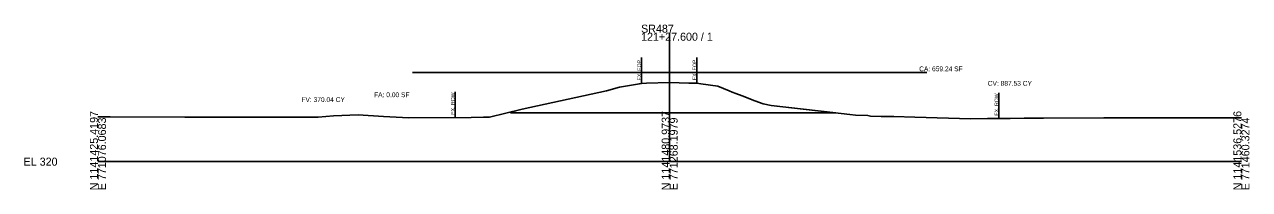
# Model space of a CAD drawing. Extents: x -26 to 5403, y -13 to 9553.
# Drawn here: x 1974.3 to 2402.8, y 1490.3 to 1547.8 of the extents above; entities that cross this region are included whole.
import ezdxf

# ---------------------------------------------------------------- set-up
doc = ezdxf.new("R2010")
doc.units = 0
for name, color, linetype in [('CONST_LV3', 7, 'Continuous'), ('Default', 7, 'Continuous'), ('Draft_XS_Grid', 7, 'Continuous'), ('DTM_X_GROUND', 7, 'Continuous'), ('X_ROW', 7, 'Continuous'), ('X_TRANS_EOP', 7, 'Continuous'), ('XS_CELL', 7, 'Continuous'), ('XS_M_SHAPES_EARTHWORK', 7, 'Continuous'), ('XS_P_GROUND', 7, 'Continuous'), ('XS_SHEET_EW_TX_AREA', 7, 'Continuous'), ('XS_SHEET_EW_TX_VOLUME', 7, 'Continuous')]:
    doc.layers.add(name, color=color, linetype=linetype)

msp = doc.modelspace()

# ---------------------------------------------------------------- linework, layer by layer
at = {"layer": 'CONST_LV3'}
msp.add_lwpolyline([(2110, 1531.09), (2203.61, 1531.09), (2290, 1531.09)], dxfattribs=at)
at = {"layer": 'Default'}
msp.add_lwpolyline([(2258.16, 1517), (2144.29, 1517)], dxfattribs=at)
at = {"layer": 'DTM_X_GROUND'}
msp.add_lwpolyline([(2000, 1515.63), (2004.26, 1515.65), (2030.42, 1515.57), (2031.08, 1515.57), (2032.62, 1515.56), (2045.53, 1515.52), (2050.03, 1515.5), (2067.52, 1515.52), (2074.21, 1515.55), (2076.99, 1515.58), (2082.43, 1515.96), (2091.05, 1516.39), (2099.92, 1515.74), (2108.8, 1515.28), (2130.54, 1515.41), (2134.86, 1515.5), (2136.99, 1515.54), (2148.35, 1518.28), (2177.9, 1524.71), (2182.46, 1525.99), (2189.4, 1527.21), (2190.2, 1527.3), (2191.87, 1527.35), (2199.91, 1527.6), (2206.67, 1527.43), (2209.54, 1527.39), (2210.87, 1527.18), (2216.89, 1526.37), (2220.82, 1524.67), (2221.82, 1524.28), (2223.15, 1523.78), (2225.37, 1522.99), (2229.75, 1521.28), (2232.68, 1520.13), (2235.47, 1519.6), (2263.04, 1516.44), (2264.99, 1516.28), (2269.3, 1516.15), (2270.3, 1515.84), (2274.04, 1515.78), (2278.41, 1515.75), (2285.77, 1515.55), (2305.39, 1514.92), (2311.2, 1515.01), (2319.17, 1515.08), (2323.96, 1515.12), (2327.61, 1515.13), (2330.72, 1515.15), (2351.86, 1515.27), (2400, 1515.35)], dxfattribs=at)
at = {"layer": 'X_ROW'}
for p, q in [((2125, 1524.37), (2125, 1515.37)), ((2315.18, 1524.04), (2315.18, 1515.04))]:
    msp.add_line(p, q, dxfattribs=at)
at = {"layer": 'X_TRANS_EOP'}
for p, q in [((2190.2, 1536.3), (2190.2, 1527.3)), ((2209.54, 1536.39), (2209.54, 1527.39))]:
    msp.add_line(p, q, dxfattribs=at)
at = {"layer": 'XS_CELL'}
for p, q in [((2200, 1500), (2200, 1545)), ((2000, 1500), (2200, 1500)), ((2200, 1500), (2400, 1500))]:
    msp.add_line(p, q, dxfattribs=at)
at = {"layer": 'XS_M_SHAPES_EARTHWORK'}
msp.add_lwpolyline([(2144.29, 1517), (2144.29, 1517.3), (2148.35, 1518.28), (2177.9, 1524.71), (2182.46, 1525.99), (2189.4, 1527.21), (2190.2, 1527.3), (2191.87, 1527.35), (2199.91, 1527.6), (2206.67, 1527.43), (2209.54, 1527.39), (2210.87, 1527.18), (2216.89, 1526.37), (2220.82, 1524.67), (2221.82, 1524.28), (2223.15, 1523.78), (2225.37, 1522.99), (2229.75, 1521.28), (2232.68, 1520.13), (2235.47, 1519.6), (2258.16, 1517), (2258.11, 1517), (2258.1, 1517), (2258.04, 1517), (2258.01, 1517), (2206.99, 1517), (2197.96, 1517), (2194.94, 1517), (2144.77, 1517), (2144.5, 1517), (2144.3, 1517)], close=True, dxfattribs=at)
at = {"layer": 'XS_P_GROUND'}
msp.add_lwpolyline([(2144.29, 1517), (2144.3, 1517), (2144.5, 1517), (2144.77, 1517), (2194.94, 1517), (2197.96, 1517), (2206.99, 1517), (2258.01, 1517), (2258.04, 1517), (2258.1, 1517), (2258.11, 1517), (2258.16, 1517)], dxfattribs=at)

# ---------------------------------------------------------------- texts
at = {"layer": 'Draft_XS_Grid'}
msp.add_text('-', height=0.0001, dxfattribs=at).set_placement((2000, 1500))
at = {"layer": 'X_ROW'}
for p in [(2124.8, 1516.37), (2314.98, 1516.04)]:
    msp.add_text('EX. ROW', height=1.3, rotation=90, dxfattribs=at).set_placement(p)
at = {"layer": 'X_TRANS_EOP'}
for p in [(2190, 1528.3), (2209.34, 1528.39)]:
    msp.add_text('EX. EOP', height=1.3, rotation=90, dxfattribs=at).set_placement(p)
at = {"layer": 'XS_CELL'}
for s, p in [('SR487', (2190, 1545)), ('121+27.600 / 1', (2190, 1542.2)), ('EL 320', (1974, 1498.6))]:
    msp.add_text(s, height=2.8, dxfattribs=at).set_placement(p)
for s, p in [('N 1141425.4197', (2000, 1490)), ('N 1141480.9737', (2200, 1490)), ('N 1141536.5276', (2400, 1490)), ('E 771076.0683', (2002.8, 1490)), ('E 771268.1979', (2202.8, 1490)), ('E 771460.3274', (2402.8, 1490))]:
    msp.add_text(s, height=2.8, rotation=90, dxfattribs=at).set_placement(p)
at = {"layer": 'XS_SHEET_EW_TX_AREA'}
for s, p in [('CA: 659.24 SF', (2287.28, 1531.54)), ('FA: 0.00 SF', (2096.6, 1522.5))]:
    msp.add_text(s, height=1.68, dxfattribs=at).set_placement(p)
at = {"layer": 'XS_SHEET_EW_TX_VOLUME'}
for s, p in [('CV: 887.53 CY', (2311.27, 1526.5)), ('FV: 370.04 CY', (2071.18, 1520.82))]:
    msp.add_text(s, height=1.68, dxfattribs=at).set_placement(p)

doc.saveas('drawing.dxf')
